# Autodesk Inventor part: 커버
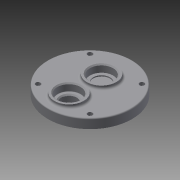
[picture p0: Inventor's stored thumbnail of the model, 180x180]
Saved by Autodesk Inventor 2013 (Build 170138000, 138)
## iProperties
Created: 2015-07
Part Number: 커버
Material: 일반
Document SubType Name: Modeling
Designer: user
Density: 1 g/cm^3
Author: user
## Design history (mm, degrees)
sketch "스케치1"
  geometry: C1 r 40 at (0, 0); 1 further point
  constraints: 1 centre point, 1 coincident
  dimensions: "d0" = 40 radius of C1
extrude "돌출1" new body sketch "스케치1" stored distance "d1" = 9; taper "d2" = 0 deg
sketch "스케치2" dims "d3" = 35
  geometry: L1 (0, 0)-(24.749, 24.749); L2 (0, 0)-(35, 0); L3 (0, 0)-(0, 15.367); L4 (0, 0)-(17.5, 0); C1 r 40 at (0, 0) reference; C2 r 4 at (24.749, 24.749); C3 r 4 at (24.749, -24.749); C4 r 4 at (-24.749, 24.749); C5 r 4 at (-24.749, -24.749)
  constraints: 8 end point, 4 centre point, 3 symmetric about line, 2 coincident, 1 equal length, 1 horizontal, 1 midpoint, 1 perpendicular, 6 other
  dimensions: "d4" = 45 deg angle of L2 L1; "d5" = 4 radius of C2
extrude "돌출2" cut sketch "스케치2" distance "d6" = 4.4; taper "d7" = 0 deg
sketch "스케치3"
  geometry: L1 (24.749, -24.749)-(24.749, -15.255); L2 (24.749, -24.749)-(34.935, -24.749); C1 r 4 at (0, 0) reference; C2 r 2.25 at (0, 0); C3 r 2.25 at (49.497, 0); C4 r 2.25 at (0, -49.497); C5 r 2.25 at (49.497, -49.497)
  constraints: 4 centre point, 4 end point, 3 symmetric about line, 1 coincident, 1 perpendicular, 1 vertical, 3 other
  dimensions: "d8" = 2.25 radius of C2
extrude "돌출3" cut sketch "스케치3" distance "d9" = 12.4; taper "d10" = 0 deg
sketch "스케치4"
  geometry: L1 (0, 0)-(0, -20); L2 (0, 0)-(0, 11); C1 r 40 at (0, 0) reference; C2 r 14 at (0, 11); C3 r 14 at (0, -20)
  constraints: 4 end point, 2 centre point, 2 coincident, 1 collinear, 1 vertical
  dimensions: "d11" = 20 distance of L1.start L1.end; "d12" = 11 distance of L1.start L2.end; "d13" = 14 radius of C2; "d14" = 14 radius of C3
extrude "돌출4" join sketch "스케치4" distance "d15" = 3; taper "d16" = 0 deg
sketch "스케치5"
  geometry: C1 r 14 at (0, 0) reference; C2 r 11 at (0, 0); 1 further point
  constraints: 1 centre point, 1 coincident
  dimensions: "d17" = 11 radius of C2
extrude "돌출5" cut sketch "스케치5" distance "d18" = 7; taper "d19" = 0 deg
sketch "스케치6"
  geometry: C1 r 8 at (0, 0); 2 further points
  constraints: 1 centre point, 1 coincident, 1 vertical alignment
  dimensions: "d20" = 8 radius of C1
extrude "돌출6" cut sketch "스케치6" distance "d21" = 1; taper "d22" = 0 deg
sketch "스케치7"
  geometry: C1 r 14 at (0, 0) reference; C2 r 11 at (0, 0); 1 further point
  constraints: 1 centre point, 1 coincident
  dimensions: "d23" = 11 radius of C2
extrude "돌출7" cut sketch "스케치7" distance "d24" = 7; taper "d25" = 0 deg
sketch "스케치8"
  geometry: C1 r 11 at (0, 0) reference; C2 r 7.5 at (0, 0); 1 further point
  constraints: 1 centre point, 1 coincident
  dimensions: "d26" = 7.5 radius of C2
extrude "돌출8" cut sketch "스케치8" distance "d27" = 2; taper "d28" = 0 deg
sketch "스케치9"
  geometry: L1 (0, 0)-(0, -20); C1 r 40 at (0, 0) reference; C2 r 15 at (0, -20)
  constraints: 2 end point, 1 centre point, 1 coincident, 1 vertical
  dimensions: "d29" = 20 distance of L1.start L1.end; "d30" = 15 radius of C2
extrude "돌출9" join sketch "스케치9" distance "d31" = 4; taper "d32" = 0 deg
sketch "스케치10"
  geometry: C1 r 15 at (0, 0) reference; C2 r 11 at (0, 0); 1 further point
  constraints: 1 centre point, 1 coincident
  dimensions: "d33" = 11 radius of C2
extrude "돌출10" cut sketch "스케치10" distance "d34" = 7; taper "d35" = 0 deg
fillet "모깎기1" dims "d36" = 2
chamfer "모따기1" distance "d37" = 1; stored, may be unused: second distance "d38" = 2, angle "d39" = 45 deg
fillet "모깎기2" dims "d40" = 0.3
chamfer "모따기2" distance "d41" = 1; stored, may be unused: second distance "d42" = 2, angle "d43" = 45 deg
chamfer "모따기3" distance "d44" = 1; stored, may be unused: second distance "d45" = 2, angle "d46" = 45 deg
fillet "모깎기3" dims "d47" = 0.3
fillet "모깎기4" dims "d48" = 1
node "솔리드1"
